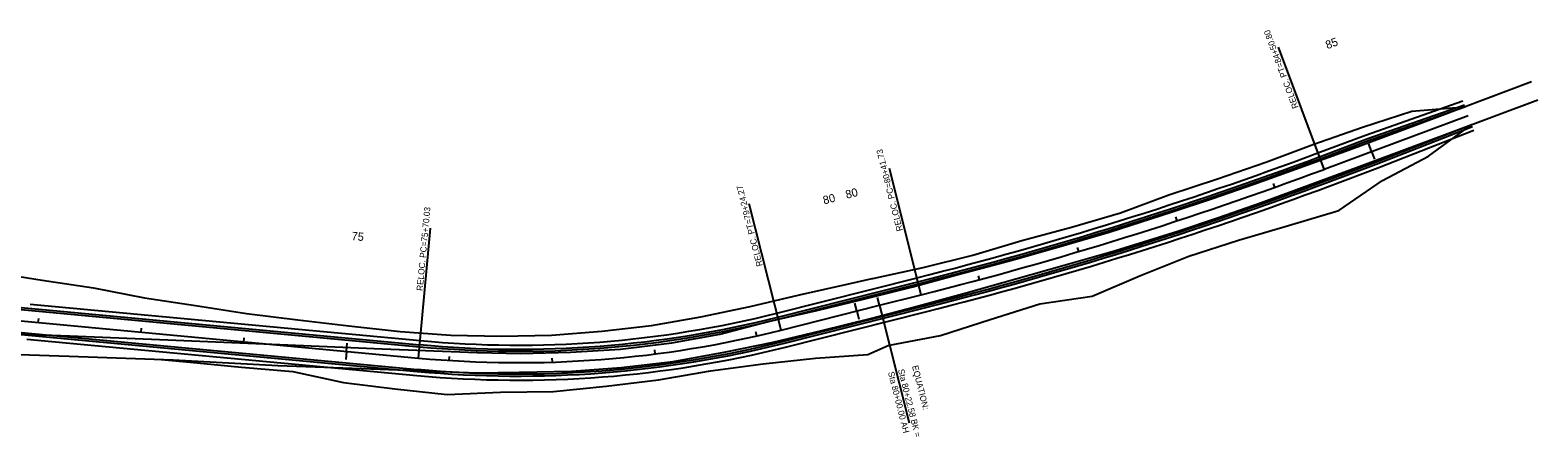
# Model space of a CAD drawing. Extents: x 1965724 to 1970311, y 1117080 to 1118208.
# Drawn here: x 1968850 to 1970311, y 1117813 to 1118208 of the extents above; entities that cross this region are included whole.
import ezdxf

# ---------------------------------------------------------------- set-up
doc = ezdxf.new("R2010")
doc.units = 0
for name, color, linetype in [('RD_EX_Road', 7, 'Continuous'), ('RD_EX_RW', 7, 'Continuous'), ('RD_HC_CL_Rel', 7, 'Continuous'), ('RD_HC_Data_Rel', 7, 'Continuous'), ('RD_HC_Data_Tic_Rel', 7, 'Continuous'), ('RD_HC_TX_Rel_Sta50', 7, 'Continuous'), ('RD_PD_EarthShd', 7, 'Continuous'), ('RD_PD_Final_TrvlWay', 7, 'Continuous'), ('RD_PD_PaveShd', 7, 'Continuous'), ('RD_PD_RW', 7, 'Continuous')]:
    doc.layers.add(name, color=color, linetype=linetype)

msp = doc.modelspace()

# ---------------------------------------------------------------- linework, layer by layer
at = {"layer": 'RD_EX_Road'}
for points in [[(1969956, 1118031.2), (1969996, 1118044.6), (1970036.1, 1118058.4), (1970128.5, 1118091.9), (1970215.9, 1118124.3), (1970305.1, 1118158)], [(1969962.3, 1118013), (1970001.8, 1118026.3), (1970042.5, 1118040.4), (1970135.4, 1118074.7), (1970224, 1118107.7), (1970311.2, 1118140.2)], [(1969810.8, 1117987.5), (1969847, 1117997.6), (1969895.7, 1118011.9), (1969956, 1118031.2)], [(1969282.9, 1117875.4), (1969323.9, 1117876.1), (1969374.9, 1117877.1), (1969422.8, 1117880.6), (1969473.4, 1117886.6), (1969522.6, 1117895.5), (1969570.2, 1117905.2), (1969616.1, 1117916.1), (1969665.8, 1117928.6), (1969710.9, 1117940.6), (1969757.1, 1117953.2), (1969805.3, 1117966.7), (1969852.3, 1117979.8), (1969901.9, 1117994.1), (1969962.3, 1118013)], [(1969283.3, 1117895.4), (1969325.6, 1117894.4), (1969373.8, 1117895.6), (1969422.2, 1117898.6), (1969472.1, 1117904.7), (1969518.5, 1117913.1), (1969565.2, 1117925.2), (1969612.4, 1117936.1), (1969659.1, 1117947.3), (1969705.6, 1117959), (1969751.6, 1117971.4), (1969799.2, 1117984.2), (1969810.8, 1117987.5)], [(1968530.5, 1117925.7), (1968682, 1117919), (1968783.2, 1117915.4), (1968888.6, 1117911.4), (1968991.2, 1117907.1), (1969092, 1117903.1), (1969191.1, 1117898.7), (1969283.3, 1117895.4)], [(1968527.8, 1117906.4), (1968680.8, 1117899.1), (1968781.7, 1117895.4), (1968887.9, 1117891.8), (1968988.7, 1117888.2), (1969090.1, 1117882.8), (1969189.3, 1117879), (1969282.9, 1117875.4)]]:
    msp.add_lwpolyline(points, dxfattribs=at)
at = {"layer": 'RD_EX_RW'}
for points in [[(1969956, 1118031.2), (1969996, 1118044.6), (1970036.1, 1118058.4), (1970128.5, 1118091.9), (1970215.9, 1118124.3), (1970305.1, 1118158)], [(1969962.3, 1118013), (1970001.8, 1118026.3), (1970042.5, 1118040.4), (1970135.4, 1118074.7), (1970224, 1118107.7), (1970311.2, 1118140.2)], [(1969810.8, 1117987.5), (1969847, 1117997.6), (1969895.7, 1118011.9), (1969956, 1118031.2)], [(1969282.9, 1117875.4), (1969323.9, 1117876.1), (1969374.9, 1117877.1), (1969422.8, 1117880.6), (1969473.4, 1117886.6), (1969522.6, 1117895.5), (1969570.2, 1117905.2), (1969616.1, 1117916.1), (1969665.8, 1117928.6), (1969710.9, 1117940.6), (1969757.1, 1117953.2), (1969805.3, 1117966.7), (1969852.3, 1117979.8), (1969901.9, 1117994.1), (1969962.3, 1118013)], [(1969283.3, 1117895.4), (1969325.6, 1117894.4), (1969373.8, 1117895.6), (1969422.2, 1117898.6), (1969472.1, 1117904.7), (1969518.5, 1117913.1), (1969565.2, 1117925.2), (1969612.4, 1117936.1), (1969659.1, 1117947.3), (1969705.6, 1117959), (1969751.6, 1117971.4), (1969799.2, 1117984.2), (1969810.8, 1117987.5)], [(1968530.5, 1117925.7), (1968682, 1117919), (1968783.2, 1117915.4), (1968888.6, 1117911.4), (1968991.2, 1117907.1), (1969092, 1117903.1), (1969191.1, 1117898.7), (1969283.3, 1117895.4)], [(1968527.8, 1117906.4), (1968680.8, 1117899.1), (1968781.7, 1117895.4), (1968887.9, 1117891.8), (1968988.7, 1117888.2), (1969090.1, 1117882.8), (1969189.3, 1117879), (1969282.9, 1117875.4)]]:
    msp.add_lwpolyline(points, dxfattribs=at)
at = {"layer": 'RD_HC_CL_Rel'}
for p, q in [((1970104, 1118072.9), (1970243.8, 1118125.1)), ((1968277.4, 1117978.5), (1969226.4, 1117889.9)), ((1969673.3, 1117941), (1969713.7, 1117951.2)), ((1969577.9, 1117916.9), (1969673.3, 1117941))]:
    msp.add_line(p, q, dxfattribs=at)
for centre, radius, start, end in [((1968809, 1121539.8), 3700.9, 284.1493, 290.4823), ((1969323.3, 1118927.1), 1041.7, 264.6661, 284.1493)]:
    msp.add_arc(centre, radius, start, end, dxfattribs=at)
at = {"layer": 'RD_HC_Data_Rel'}
for p, q in [((1970104, 1118072.9), (1970059.8, 1118191.2)), ((1969713.7, 1117951.2), (1969682.8, 1118073.8)), ((1969577.9, 1117916.9), (1969547, 1118039.5)), ((1969226.4, 1117889.9), (1969238.2, 1118015.8)), ((1969673.3, 1117941), (1969702, 1117826.9))]:
    msp.add_line(p, q, dxfattribs=at)
at = {"layer": 'RD_HC_Data_Tic_Rel'}
for p, q in [((1970150.1, 1118090.1), (1970147.3, 1118097.6)), ((1970150.1, 1118090.1), (1970152.9, 1118082.6)), ((1970056.3, 1118055.4), (1970055, 1118059.2)), ((1969961.7, 1118023), (1969960.5, 1118026.8)), ((1969866.3, 1117993.1), (1969865.2, 1117997)), ((1969770.1, 1117965.9), (1969769.1, 1117969.7)), ((1969651.4, 1117935.5), (1969649.4, 1117943.2)), ((1969651.4, 1117935.5), (1969653.3, 1117927.7)), ((1969673.3, 1117941), (1969671.3, 1117948.7)), ((1969673.3, 1117941), (1969675.2, 1117933.2)), ((1968858, 1117924.3), (1968858.4, 1117928.2)), ((1968957.6, 1117915), (1968957.9, 1117918.9)), ((1969057.1, 1117905.7), (1969057.5, 1117909.6)), ((1969554.3, 1117911.3), (1969553.4, 1117915.2)), ((1969156.7, 1117896.4), (1969156, 1117888.4)), ((1969156.7, 1117896.4), (1969157.4, 1117904.3)), ((1969256.3, 1117887.5), (1969256.6, 1117891.5)), ((1969455.9, 1117893.8), (1969455.4, 1117897.8)), ((1969356.3, 1117885.9), (1969356.1, 1117889.9))]:
    msp.add_line(p, q, dxfattribs=at)
at = {"layer": 'RD_PD_EarthShd'}
for p, q in [((1970144.2, 1118106), (1970238.6, 1118139.3)), ((1970156.1, 1118074.2), (1970249.3, 1118110.7)), ((1970098.1, 1118088.8), (1970144.2, 1118106)), ((1970110, 1118056.9), (1970156.1, 1118074.2)), ((1969573.8, 1117933.4), (1969709.6, 1117967.7)), ((1968850.1, 1117942.1), (1969228, 1117906.8)), ((1969582.1, 1117900.5), (1969717.9, 1117934.7)), ((1968846.9, 1117908.2), (1969224.9, 1117872.9))]:
    msp.add_line(p, q, dxfattribs=at)
for centre, radius, start, end in [((1968809, 1121539.8), 3683.9, 284.1493, 290.4823), ((1968809, 1121539.8), 3717.9, 284.1493, 290.4823), ((1969323.3, 1118927.1), 1024.7, 264.6661, 284.1493), ((1969323.3, 1118927.1), 1058.7, 264.6661, 284.1493)]:
    msp.add_arc(centre, radius, start, end, dxfattribs=at)
at = {"layer": 'RD_PD_Final_TrvlWay'}
for p, q in [((1970146.3, 1118100.4), (1970240.6, 1118133.6)), ((1970154, 1118079.8), (1970247.1, 1118116.3)), ((1970100.2, 1118083.2), (1970146.3, 1118100.4)), ((1970107.9, 1118062.6), (1970154, 1118079.8)), ((1970154, 1118079.8), (1970154, 1118079.8)), ((1968278.4, 1117989.4), (1969227.5, 1117900.8)), ((1968276.3, 1117967.5), (1969225.4, 1117878.9)), ((1969575.2, 1117927.6), (1969711, 1117961.8)), ((1969580.6, 1117906.3), (1969716.4, 1117940.5))]:
    msp.add_line(p, q, dxfattribs=at)
for centre, radius, start, end in [((1968809, 1121539.8), 3689.9, 284.1493, 290.4823), ((1968809, 1121539.8), 3711.9, 284.1493, 290.4823), ((1969323.3, 1118927.1), 1030.7, 264.6661, 284.1493), ((1969323.3, 1118927.1), 1052.7, 264.6661, 284.1493)]:
    msp.add_arc(centre, radius, start, end, dxfattribs=at)
at = {"layer": 'RD_PD_PaveShd'}
for p, q in [((1970145.6, 1118102.3), (1970240, 1118135.5)), ((1970154.7, 1118077.9), (1970247.8, 1118114.4)), ((1970099.5, 1118085.1), (1970145.6, 1118102.3)), ((1970108.6, 1118060.7), (1970154.7, 1118077.9)), ((1968278.6, 1117991.4), (1969227.6, 1117902.8)), ((1968276.1, 1117965.5), (1969225.2, 1117876.9)), ((1969574.8, 1117929.6), (1969710.5, 1117963.8)), ((1969581.1, 1117904.3), (1969716.9, 1117938.6))]:
    msp.add_line(p, q, dxfattribs=at)
for centre, radius, start, end in [((1968809, 1121539.8), 3687.9, 284.1493, 290.4823), ((1968809, 1121539.8), 3713.9, 284.1493, 290.4823), ((1969323.3, 1118927.1), 1028.7, 264.6661, 284.1493), ((1969323.3, 1118927.1), 1054.7, 264.6661, 284.1493)]:
    msp.add_arc(centre, radius, start, end, dxfattribs=at)
at = {"layer": 'RD_PD_RW'}
for p, q in [((1970141.3, 1118113.7), (1970189, 1118129.4)), ((1970189, 1118129.4), (1970240.6, 1118133.6)), ((1970094.1, 1118097.2), (1970141.3, 1118113.7)), ((1970205.4, 1118085.5), (1970247.1, 1118116.3)), ((1970047.6, 1118079.9), (1970094.1, 1118097.2)), ((1970160.7, 1118062.2), (1970205.4, 1118085.5)), ((1970000.7, 1118063.7), (1970047.6, 1118079.9)), ((1969953.5, 1118048.1), (1970000.7, 1118063.7)), ((1970118.2, 1118033), (1970160.7, 1118062.2)), ((1969906.9, 1118030.7), (1969953.5, 1118048.1)), ((1969859.3, 1118016.8), (1969906.9, 1118030.7)), ((1970069.5, 1118018.4), (1970118.2, 1118033)), ((1969811.3, 1118003.8), (1969859.3, 1118016.8)), ((1970021, 1118004.3), (1970069.5, 1118018.4)), ((1969763.8, 1117989.5), (1969811.3, 1118003.8)), ((1969973, 1117988.8), (1970021, 1118004.3)), ((1969715.5, 1117977.8), (1969763.8, 1117989.5)), ((1969926.1, 1117969.8), (1969973, 1117988.8)), ((1968812.3, 1117973.2), (1968861.9, 1117965.3)), ((1968861.9, 1117965.3), (1968911.5, 1117958.1)), ((1969644.7, 1117962.1), (1969666.2, 1117966.9)), ((1969666.2, 1117966.9), (1969666.7, 1117967)), ((1969666.7, 1117967), (1969715.5, 1117977.8)), ((1969879.2, 1117950), (1969926.1, 1117969.8)), ((1968911.5, 1117958.1), (1968960.8, 1117948.4)), ((1969547.8, 1117940), (1969595.8, 1117951.3)), ((1969595.8, 1117951.3), (1969644.7, 1117962.1)), ((1969828.7, 1117942.3), (1969879.2, 1117950)), ((1968960.8, 1117948.4), (1969010.3, 1117940.7)), ((1969010.3, 1117940.7), (1969059.7, 1117933)), ((1969500.2, 1117929.9), (1969547.8, 1117940)), ((1969780.5, 1117927.3), (1969828.7, 1117942.3)), ((1969059.7, 1117933), (1969109.4, 1117926.8)), ((1969109.4, 1117926.8), (1969159, 1117921.2)), ((1969159, 1117921.2), (1969208.7, 1117915.7)), ((1969404, 1117915.8), (1969452.3, 1117921.4)), ((1969452.3, 1117921.4), (1969500.2, 1117929.9)), ((1969732.3, 1117911.7), (1969780.5, 1117927.3)), ((1969208.7, 1117915.7), (1969257.9, 1117912.1)), ((1969257.9, 1117912.1), (1969306.7, 1117911)), ((1969306.7, 1117911), (1969355.4, 1117911.9)), ((1969355.4, 1117911.9), (1969404, 1117915.8)), ((1969682.9, 1117902.5), (1969732.3, 1117911.7)), ((1969611.2, 1117889.6), (1969662, 1117893.3)), ((1969662, 1117893.3), (1969682.4, 1117902.4)), ((1969682.4, 1117902.4), (1969682.9, 1117902.5)), ((1968977.1, 1117888.6), (1969005.1, 1117886)), ((1969005.1, 1117886), (1969054.8, 1117881.1)), ((1969054.8, 1117881.1), (1969104.6, 1117876.8)), ((1969104.6, 1117876.8), (1969153.8, 1117866.1)), ((1969459.1, 1117868.8), (1969509.5, 1117877.5)), ((1969509.5, 1117877.5), (1969560.4, 1117884.1)), ((1969560.4, 1117884.1), (1969611.2, 1117889.6)), ((1969153.8, 1117866.1), (1969203.5, 1117860.1)), ((1969357.2, 1117857.5), (1969408.3, 1117862.5)), ((1969408.3, 1117862.5), (1969459.1, 1117868.8)), ((1969203.5, 1117860.1), (1969254.2, 1117854.5)), ((1969254.2, 1117854.5), (1969305.8, 1117856.9)), ((1969305.8, 1117856.9), (1969357.2, 1117857.5))]:
    msp.add_line(p, q, dxfattribs=at)

# ---------------------------------------------------------------- texts
at = {"layer": 'RD_HC_Data_Rel'}
for s, rotation, p in [('RELOC. PT=84+50.80', 110.4823, (1970079.4, 1118133.1)), ('RELOC. PC=80+41.73', 104.1493, (1969695.9, 1118013.7)), ('RELOC. PT=79+24.27', 104.1493, (1969560.1, 1117979.5)), ('RELOC. PC=75+70.03', 84.6661, (1969230.5, 1117954.8)), ('Sta 80+00.00 AH', 284.1493, (1969681.4, 1117876)), ('Sta 80+22.58 BK = ', 284.1493, (1969691.1, 1117878.4)), ('EQUATION:', 284.1493, (1969704.7, 1117881.9))]:
    msp.add_text(s, height=6, rotation=rotation, dxfattribs=at).set_placement(p)
at = {"layer": 'RD_HC_TX_Rel_Sta50'}
for s, rotation, p in [('85', 20.4823, (1970107.2, 1118189.3)), ('80', 14.1493, (1969641.4, 1118044.3)), ('80', 14.1493, (1969619.5, 1118038.8)), ('75', 354.6661, (1969161.3, 1118004.4))]:
    msp.add_text(s, height=8, rotation=rotation, dxfattribs=at).set_placement(p)

doc.saveas('drawing.dxf')
